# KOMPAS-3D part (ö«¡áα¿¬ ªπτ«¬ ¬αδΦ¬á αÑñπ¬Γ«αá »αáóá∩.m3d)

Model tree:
1. Эскиз:3
2. Операция выдавливания:1
     Расстояние 1 = 1
3. Эскиз:2
4. Операция выдавливания:12
     Расстояние 1 = 1
5. Эскиз:27
6. Вырезать элемент выдавливания:22
     Расстояние 1 = 1
7. Фаска:8
     Угол = 45; Длина 1 = 0.2; Длина 2 = 0.2
8. Эскиз:28
9. Вырезать элемент выдавливания:23
     Расстояние 1 = 3
10. Эскиз:29
11. Вырезать элемент выдавливания:24
     Расстояние 1 = 3
12. Эскиз:30
13. Вырезать элемент выдавливания:25
     Расстояние 1 = 3
14. Эскиз:31
15. Вырезать элемент выдавливания:26
     Расстояние 1 = 3
16. Эскиз:32
17. Вырезать элемент выдавливания:27
     Расстояние 1 = 3
18. Фаска:9
     Угол = 45; Длина 1 = 1; Длина 2 = 1
19. Эскиз:33
20. Вырезать элемент выдавливания:28
     Расстояние 1 = 3
21. Эскиз:34
22. Операция выдавливания:13
     Расстояние 1 = 4
23. Эскиз:35
24. Вырезать элемент выдавливания:29
     Расстояние 1 = 1
25. Эскиз:36
26. Вырезать элемент выдавливания:30
     Расстояние 1 = 1
27. Операция выдавливания:14
     Толщина стенки 1 = 0.4; Расстояние 1 = 4; Расстояние 2 = 2
